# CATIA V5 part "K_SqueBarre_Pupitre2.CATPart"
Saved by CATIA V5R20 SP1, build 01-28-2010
Part number: squelette_barre_pupitre_2
Publications: "Point.1", "Point.2", "Plan.1", "Droite.1", "Droite.2", "Droite.3"
Bounding box of the stored display mesh (mm): x 0 to 20, y 0 to 0, z 0 to 200
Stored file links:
  G:\Khaled_CFAO_2011\ST2M\ST2M_GR2\gcausse\Khaled\CAD_ThinkMotion\K_SqueBarre_Pupitre2.CATPart
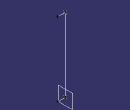
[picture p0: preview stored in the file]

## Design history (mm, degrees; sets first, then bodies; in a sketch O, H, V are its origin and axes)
Set1
  Point1: (0, 0, 0)
  Point2: (0, 0, 200)
  Plane1: type Offset, RefPlane yz-plane, Offset 0
  Line1: type PtPt, FirstPoint Point1, SecondPoint Point2
  Line2: type PtDir, RefPoint Point1, Direction Plane1, Start 0, End 20
  Line3: type PtDir, RefPoint Point2, Direction Plane1, Start 0, End 20
Body1 (main body)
